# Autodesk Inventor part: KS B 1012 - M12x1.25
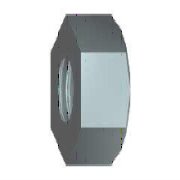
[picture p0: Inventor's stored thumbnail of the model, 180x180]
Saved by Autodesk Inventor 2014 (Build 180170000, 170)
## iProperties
IsCustomPart: 0
Created: 2009-02
Part Number: KS B 1012 - M12x1.25
Material: 강, 연강
Description: 6각 너트
Document SubType Name: Modeling
Standard: KS B 1012
Designer: KYOUNG IL JANG
Standards Organization: KS
Language: ko-KR
Size Designation: M12x1.25
Categories: <MemberInstance><Categories><Category DisplayName="조임쇠" InternalName="e4da775c-781d-43d5-af7c-5136215cf5a6" Mnemonic="FSTN"><Category DisplayName="너트" InternalN
Density: 1 g/cm^3
Appearance: 강철
Author: KYOUNG IL JANG
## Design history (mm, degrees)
sketch "스케치1"
  geometry: L1 (10.97, 0)-(5.485, -9.5); L2 (5.485, -9.5)-(-5.485, -9.5); L3 (-5.485, -9.5)-(-10.97, 0); L4 (-10.97, 0)-(-5.485, 9.5); L5 (-5.485, 9.5)-(5.485, 9.5); L6 (5.485, 9.5)-(10.97, 0); 2 further points
  constraints: 12 end point, 1 coincident, 1 horizontal, 11 other
  dimensions: "d0" = 21.93931 distance of L1.start L3.end (= 1.1547 x SW)
extrude "본체" new body sketch "스케치1" distance "d1" = 10 (= KOH); taper "d2" = 0 deg
sketch "스케치2"
  geometry: 1 further point
hole "스레드" sketch "스케치2" diameter "d6" = 10.647; stored, may be unused: countersink angle "d10" = 82 deg, drill point angle "d12" = 118 deg; dims "d7" = 12.7, "d8" = 9.525, "d9" = 6.35, "d11" = 19.05
sketch "스케치3"
  geometry: L1 (0, 10.97)-(10, 10.97) reference; L2 (10, 5.485)-(10, 10.97) reference; L3 (-2, 0)-(12, 0) reference; L4 (9.151, 10.97)-(10, 9.5)
  constraints: 2 end point, 2 point on line
  dimensions: "d3" = 19 diameter of L4.end L3 (= SW01); "d4" = 30 deg angle of L2 L4 (= ANG2)
revolve "모따기3" sketch "스케치3" stored, may be unused: angle "d5" = 90 deg
workaxis "Work Axis1"
workplane "Work Plane1"
body "Solid1"
chamfer "모따기1" distance "d13" = 0.67658 (= -0.5 x GD1 + 0.5 x NND); stored, may be unused: angle "d14" = 30 deg, second distance "d21" = 0.67658 (= -0.5 x GD1 + 0.5 x NND)
chamfer "모따기2" distance "d15" = 0.67658 (= -0.5 x GD1 + 0.5 x NND); stored, may be unused: angle "d16" = 30 deg, second distance "d22" = 0.67658 (= -0.5 x GD1 + 0.5 x NND)
other parameters: "ANG2" = 30 deg [user parameter; used in 1 equation term], "NND" = 12 [user parameter; used in 4 equation terms], "KOH" = 10 [user parameter; used in 1 equation term], "SW" = 19 [user parameter; used in 3 equation terms], "SW01" = 19 (= SW) [user parameter; used in 1 equation term], "GD1" = 10.64684 (computed from THREADDIA, PTC, TOA) [user parameter; used in 4 equation terms], "d19" = 0, "d20" = 0, "d24" = 0, "d25" = 0, "GUL" = 0.67658 (= 0.541266 x PTC) [user parameter], "TPU" = 8 (computed from PTC) [user parameter], "TOA" = 30 deg [user parameter; used in 1 equation term], "PTC" = 1.25 [user parameter; used in 4 equation terms], "E0" = 21.945 (= 1.155 x SW) [user parameter], "THREADDIA" = 12 [user parameter; used in 1 equation term], "GAL" = 0.67658 (= 0.541266 x PTC) [user parameter]
